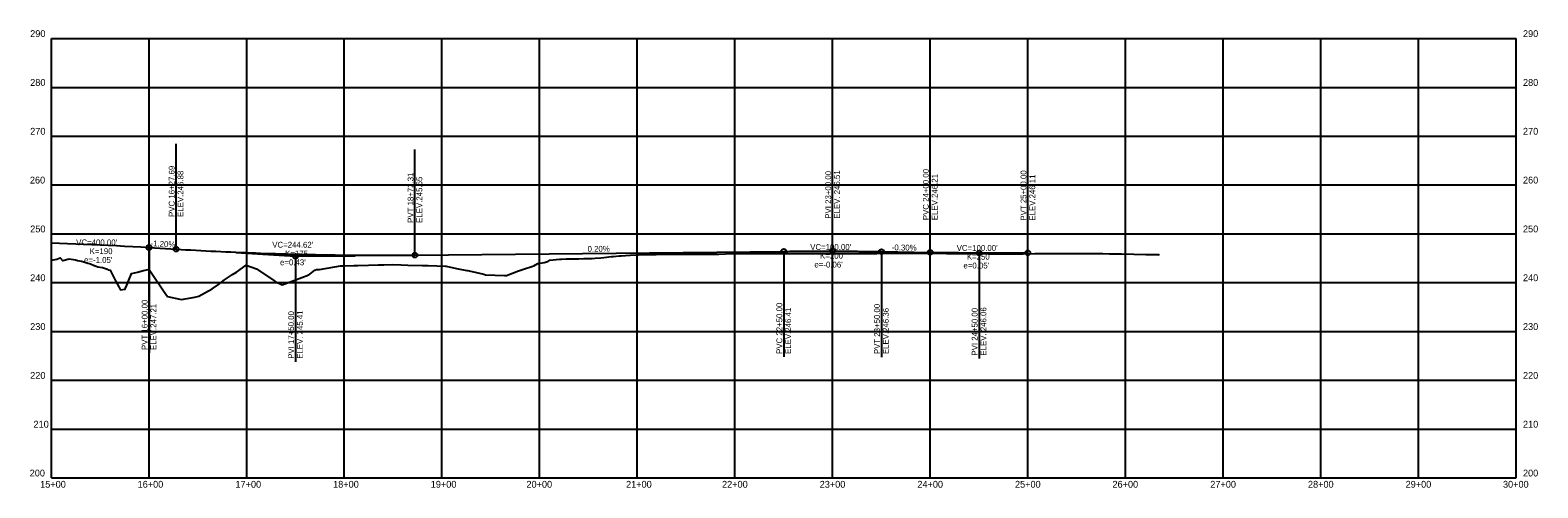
# Model space of a CAD drawing. Extents: x 1939726 to 1943270, y 529766 to 530234.
# Drawn here: x 1941726 to 1943270, y 529766 to 530234 of the extents above; entities that cross this region are included whole.
import ezdxf

# ---------------------------------------------------------------- set-up
doc = ezdxf.new("R2010")
doc.units = 0
for name, color, linetype in [('R_Axis', 7, 'Continuous'), ('R_Axis Annot', 7, 'Continuous'), ('R_Exist Surface', 7, 'Continuous'), ('R_Grid', 7, 'Continuous'), ('R_Vert Alg', 7, 'Continuous'), ('R_Vert Alg Annot', 7, 'Continuous')]:
    doc.layers.add(name, color=color, linetype=linetype)

msp = doc.modelspace()

# ---------------------------------------------------------------- linework, layer by layer
at = {"layer": 'R_Axis'}
for p, q in [((1941747.8, 529775.8), (1941747.8, 530225.8)), ((1943247.8, 529775.8), (1943247.8, 530225.8)), ((1941747.8, 529775.8), (1943247.8, 529775.8))]:
    msp.add_line(p, q, dxfattribs=at)
at = {"layer": 'R_Exist Surface'}
msp.add_lwpolyline([(1941747.8, 529998.9), (1941753.4, 529999.8), (1941753.4, 529999.8), (1941756.7, 530001.3), (1941759.4, 529998.3), (1941759.7, 529998.4), (1941766, 530000.3), (1941766.1, 530000.3), (1941772.4, 529999), (1941774.6, 529998.6), (1941778.8, 529997.7), (1941780.9, 529997.2), (1941785.1, 529995.8), (1941787.8, 529994.9), (1941791.5, 529993.4), (1941793.8, 529992.5), (1941795.5, 529992), (1941797.8, 529991.6), (1941800.2, 529991.2), (1941804.1, 529990), (1941805.1, 529989.7), (1941806.1, 529989), (1941808.1, 529988.6), (1941810.5, 529983.7), (1941813.4, 529977.7), (1941816.8, 529971.5), (1941818.4, 529968.7), (1941818.6, 529968.5), (1941823, 529969.2), (1941823.2, 529969.2), (1941823.2, 529969.3), (1941823.8, 529970.2), (1941825, 529973.3), (1941827.8, 529980), (1941829.5, 529984), (1941830, 529985.1), (1941835.9, 529986.6), (1941842.2, 529988.2), (1941847, 529989.3), (1941848.2, 529988.6), (1941848.5, 529988.2), (1941850.7, 529985), (1941862.5, 529967.3), (1941866.7, 529961.5), (1941879.2, 529959), (1941881, 529958.4), (1941894.7, 529960.8), (1941898.8, 529961.9), (1941912.6, 529969.4), (1941919.1, 529974), (1941925.1, 529978.7), (1941933.4, 529984.1), (1941937.3, 529986.6), (1941947.4, 529993.7), (1941957.7, 529990.1), (1941976.5, 529977.3), (1941976.8, 529977.2), (1941976.9, 529977.1), (1941977, 529977.1), (1941984.2, 529973.7), (1942004.2, 529981.2), (1942011.4, 529983.9), (1942012.4, 529984.6), (1942017.5, 529988.5), (1942019.4, 529989.1), (1942022.5, 529989.2), (1942044, 529993.1), (1942046.1, 529993.1), (1942057.7, 529993.5), (1942061.7, 529993.5), (1942072.6, 529993.8), (1942082.4, 529994.1), (1942088.3, 529994), (1942097.2, 529994.3), (1942105.9, 529994), (1942113, 529993.7), (1942127.8, 529993.4), (1942131.3, 529993.3), (1942133.6, 529993.2), (1942151.5, 529992.8), (1942151.8, 529992.8), (1942152.2, 529992.7), (1942162.6, 529990.3), (1942173.3, 529988.3), (1942174.2, 529988.2), (1942175.6, 529987.9), (1942190.7, 529984.4), (1942192.5, 529983.9), (1942202.1, 529983.4), (1942211.9, 529983.2), (1942213, 529983.2), (1942214, 529983.2), (1942226.3, 529987.8), (1942228.3, 529988.6), (1942228.7, 529988.7), (1942229.4, 529988.9), (1942241.7, 529993), (1942246, 529995.3), (1942252.3, 529996.5), (1942256.1, 529997.3), (1942258.2, 529998.9), (1942268, 529999.7), (1942269.4, 529999.8), (1942269.9, 529999.8), (1942270.3, 529999.9), (1942274.9, 530000.3), (1942287.8, 530000.1), (1942292.9, 530000.4), (1942301.6, 530000.5), (1942304.7, 530000.7), (1942310.5, 530001.2), (1942313.6, 530001.5), (1942321.5, 530002.4), (1942322.5, 530002.5), (1942323.3, 530002.6), (1942329.2, 530003.2), (1942331.4, 530003.3), (1942335.7, 530003.5), (1942340.3, 530003.8), (1942340.6, 530003.8), (1942349.2, 530004.3), (1942352.8, 530004.6), (1942358, 530004.6), (1942358.1, 530004.6), (1942359.2, 530004.6), (1942367, 530004.7), (1942375.9, 530004.8), (1942378.1, 530004.8), (1942383.5, 530004.9), (1942384.8, 530004.9), (1942393.7, 530004.9), (1942397.9, 530004.9), (1942402.6, 530005), (1942407.6, 530005), (1942411.5, 530005), (1942420.4, 530005.1), (1942421.7, 530005.1), (1942429.3, 530005.1), (1942431.4, 530005.1), (1942438.2, 530005.3), (1942447.1, 530005.5), (1942450.6, 530005.5), (1942456, 530005.6), (1942456.1, 530005.6), (1942459.9, 530005.6), (1942464.9, 530005.6), (1942473.8, 530005.6), (1942475.6, 530005.6), (1942482.7, 530005.5), (1942491.6, 530005.5), (1942493.5, 530005.5), (1942494.9, 530005.5), (1942500.5, 530005.5), (1942509.4, 530005.6), (1942518.3, 530005.6), (1942519.4, 530005.6), (1942519.7, 530005.6), (1942520, 530005.6), (1942527.2, 530005.7), (1942527.9, 530005.7), (1942536.1, 530005.7), (1942544.3, 530005.7), (1942544.5, 530005.7), (1942545, 530005.7), (1942553.9, 530005.7), (1942568, 530005.8), (1942568.6, 530005.8), (1942569.3, 530005.8), (1942592.7, 530005.8), (1942593.2, 530005.8), (1942616.7, 530006), (1942616.8, 530006), (1942616.9, 530006), (1942626.4, 530006), (1942640.8, 530006.1), (1942641, 530006.1), (1942664.4, 530005.8), (1942664.9, 530005.8), (1942665.4, 530005.8), (1942688.4, 530005.5), (1942689.1, 530005.5), (1942708.3, 530005.4), (1942709.8, 530005.4), (1942728.7, 530005.3), (1942730.4, 530005.3), (1942742.1, 530005.4), (1942743, 530005.4), (1942754.9, 530005.5), (1942755.6, 530005.5), (1942767.7, 530005.5), (1942768.2, 530005.6), (1942780.5, 530005.6), (1942780.8, 530005.6), (1942793.2, 530005.6), (1942793.6, 530005.6), (1942806, 530005.5), (1942818.6, 530005.5), (1942818.7, 530005.5), (1942824.4, 530005.5), (1942831.3, 530005.4), (1942839.8, 530005.3), (1942843.8, 530005.2), (1942843.8, 530005.2), (1942856.2, 530005), (1942856.3, 530005), (1942868.7, 530004.7), (1942868.9, 530004.7), (1942881.2, 530004.5), (1942881.4, 530004.5), (1942881.9, 530003.5)], dxfattribs=at)
at = {"layer": 'R_Grid'}
for p, q in [((1941747.8, 530225.8), (1943247.8, 530225.8)), ((1941747.8, 530225.8), (1943247.8, 530225.8)), ((1941847.8, 529775.8), (1941847.8, 530225.8)), ((1941947.8, 529775.8), (1941947.8, 530225.8)), ((1942047.8, 529775.8), (1942047.8, 530225.8)), ((1942147.8, 529775.8), (1942147.8, 530225.8)), ((1942247.8, 529775.8), (1942247.8, 530225.8)), ((1942347.8, 529775.8), (1942347.8, 530225.8)), ((1942447.8, 529775.8), (1942447.8, 530225.8)), ((1942547.8, 529775.8), (1942547.8, 530225.8)), ((1942647.8, 529775.8), (1942647.8, 530225.8)), ((1942747.8, 529775.8), (1942747.8, 530225.8)), ((1942847.8, 529775.8), (1942847.8, 530225.8)), ((1942947.8, 529775.8), (1942947.8, 530225.8)), ((1943047.8, 529775.8), (1943047.8, 530225.8)), ((1943147.8, 529775.8), (1943147.8, 530225.8)), ((1941747.8, 530175.8), (1943247.8, 530175.8)), ((1941747.8, 530125.8), (1943247.8, 530125.8)), ((1941747.8, 530075.8), (1943247.8, 530075.8)), ((1941747.8, 530025.8), (1943247.8, 530025.8)), ((1941747.8, 529975.8), (1943247.8, 529975.8)), ((1941747.8, 529925.8), (1943247.8, 529925.8)), ((1941747.8, 529875.8), (1943247.8, 529875.8)), ((1941747.8, 529825.8), (1943247.8, 529825.8))]:
    msp.add_line(p, q, dxfattribs=at)
at = {"layer": 'R_Vert Alg'}
for p, q in [((1941847.8, 530011.8), (1941875.5, 530010.1)), ((1941936.6, 530006.5), (1941997.8, 530002.8)), ((1942120.1, 530004), (1942497.8, 530007.8)), ((1942522.8, 530008.1), (1942547.8, 530008.3)), ((1942547.8, 530008.3), (1942572.8, 530007.9)), ((1942597.8, 530007.6), (1942647.8, 530006.8)), ((1942672.8, 530006.4), (1942697.8, 530006.1)), ((1942697.8, 530006.1), (1942722.8, 530006.2)), ((1941997.8, 530002.8), (1942058.9, 530003.4))]:
    msp.add_line(p, q, dxfattribs=at)
for points in [[(1941747.8, 530016.5), (1941756.1, 530016.2), (1941764.4, 530015.9), (1941772.8, 530015.6), (1941781.1, 530015.2), (1941789.4, 530014.9), (1941797.8, 530014.5), (1941806.1, 530014.1), (1941814.4, 530013.7), (1941822.8, 530013.2), (1941831.1, 530012.8), (1941839.4, 530012.3), (1941847.8, 530011.8)], [(1941875.5, 530010.1), (1941880.6, 530009.8), (1941885.6, 530009.5), (1941890.7, 530009.3), (1941895.8, 530009), (1941900.9, 530008.7), (1941906, 530008.4), (1941911.1, 530008.2), (1941916.2, 530007.9), (1941921.3, 530007.7), (1941926.4, 530007.5), (1941931.5, 530007.2), (1941936.6, 530007), (1941941.7, 530006.8), (1941946.8, 530006.6), (1941951.9, 530006.4), (1941957, 530006.2), (1941962.1, 530006), (1941967.2, 530005.8), (1941972.3, 530005.7), (1941977.4, 530005.5), (1941982.5, 530005.4), (1941987.6, 530005.2), (1941992.7, 530005.1), (1942002.9, 530004.8), (1942008, 530004.7), (1942013.1, 530004.6), (1942018.2, 530004.5), (1942023.2, 530004.4), (1942028.3, 530004.3), (1942033.4, 530004.2), (1942038.5, 530004.2), (1942043.6, 530004.1), (1942048.7, 530004), (1942053.8, 530004), (1942058.9, 530004), (1942064, 530003.9), (1942069.1, 530003.9), (1942074.2, 530003.9), (1942079.3, 530003.9), (1942084.4, 530003.9), (1942089.5, 530003.9), (1942094.6, 530003.9), (1942099.7, 530003.9), (1942104.8, 530003.9), (1942109.9, 530003.9), (1942115, 530004), (1942120.1, 530004)], [(1942497.8, 530007.8), (1942499.8, 530007.8), (1942501.9, 530007.8), (1942504, 530007.9), (1942506.1, 530007.9), (1942508.2, 530007.9), (1942510.3, 530007.9), (1942512.3, 530007.9), (1942514.4, 530007.9), (1942516.5, 530007.9), (1942518.6, 530008), (1942520.7, 530008), (1942522.8, 530008), (1942524.8, 530008), (1942526.9, 530008), (1942529, 530008), (1942531.1, 530008), (1942533.2, 530008), (1942535.3, 530008), (1942537.3, 530008), (1942539.4, 530008), (1942541.5, 530008), (1942543.6, 530008), (1942545.7, 530008), (1942549.8, 530008), (1942551.9, 530008), (1942554, 530008), (1942556.1, 530008), (1942558.2, 530008), (1942560.3, 530007.9), (1942562.3, 530007.9), (1942564.4, 530007.9), (1942566.5, 530007.9), (1942568.6, 530007.9), (1942570.7, 530007.9), (1942572.8, 530007.9), (1942574.8, 530007.8), (1942576.9, 530007.8), (1942579, 530007.8), (1942581.1, 530007.8), (1942583.2, 530007.7), (1942585.3, 530007.7), (1942587.3, 530007.7), (1942589.4, 530007.7), (1942591.5, 530007.6), (1942593.6, 530007.6), (1942595.7, 530007.6), (1942597.8, 530007.6)], [(1942647.8, 530006.8), (1942649.8, 530006.8), (1942651.9, 530006.7), (1942654, 530006.7), (1942656.1, 530006.7), (1942658.2, 530006.7), (1942660.3, 530006.6), (1942662.3, 530006.6), (1942664.4, 530006.6), (1942666.5, 530006.6), (1942668.6, 530006.5), (1942670.7, 530006.5), (1942672.8, 530006.5), (1942674.8, 530006.5), (1942676.9, 530006.5), (1942679, 530006.4), (1942681.1, 530006.4), (1942683.2, 530006.4), (1942685.3, 530006.4), (1942687.3, 530006.4), (1942689.4, 530006.4), (1942691.5, 530006.3), (1942693.6, 530006.3), (1942695.7, 530006.3), (1942699.8, 530006.3), (1942701.9, 530006.3), (1942704, 530006.3), (1942706.1, 530006.3), (1942708.2, 530006.3), (1942710.3, 530006.3), (1942712.3, 530006.3), (1942714.4, 530006.3), (1942716.5, 530006.2), (1942718.6, 530006.2), (1942720.7, 530006.2), (1942722.8, 530006.2), (1942724.8, 530006.2), (1942726.9, 530006.2), (1942729, 530006.2), (1942731.1, 530006.3), (1942733.2, 530006.3), (1942735.3, 530006.3), (1942737.3, 530006.3), (1942739.4, 530006.3), (1942741.5, 530006.3), (1942743.6, 530006.3), (1942745.7, 530006.3), (1942747.8, 530006.3)]]:
    msp.add_lwpolyline(points, dxfattribs=at)
at = {"layer": 'R_Vert Alg Annot'}
for p, q in [((1941875.5, 530040.1), (1941875.5, 530118.1)), ((1942547.8, 530038.3), (1942547.8, 530116.3)), ((1942647.8, 530036.8), (1942647.8, 530114.8)), ((1942747.8, 530036.3), (1942747.8, 530114.3)), ((1942120.1, 530034), (1942120.1, 530112)), ((1941875.5, 530010.1), (1941875.5, 530040.1)), ((1942547.8, 530008.3), (1942547.8, 530038.3)), ((1942120.1, 530004), (1942120.1, 530034)), ((1942647.8, 530006.8), (1942647.8, 530036.8)), ((1942747.8, 530006.3), (1942747.8, 530036.3)), ((1941847.8, 530011.8), (1941847.8, 529981.8)), ((1942497.8, 530007.8), (1942497.8, 529977.8)), ((1942597.8, 530007.6), (1942597.8, 529977.6)), ((1942697.8, 530006.1), (1942697.8, 529976.1)), ((1941997.8, 530002.8), (1941997.8, 529972.8)), ((1941847.8, 529981.8), (1941847.8, 529903.8)), ((1942497.8, 529977.8), (1942497.8, 529899.8)), ((1942597.8, 529977.6), (1942597.8, 529899.6)), ((1942697.8, 529976.1), (1942697.8, 529898.1)), ((1941997.8, 529972.8), (1941997.8, 529894.8))]:
    msp.add_line(p, q, dxfattribs=at)
for centre in [(1941847.8, 530011.8), (1941875.5, 530010.1), (1942120.1, 530004), (1942497.8, 530007.8), (1942547.8, 530008.3), (1942597.8, 530007.6), (1942647.8, 530006.8), (1942697.8, 530006.1), (1942747.8, 530006.3), (1941997.8, 530002.8)]:
    msp.add_circle(centre, 2.5, dxfattribs=at)

# ---------------------------------------------------------------- texts
at = {"layer": 'R_Axis Annot'}
for s, height, p in [('290', 7, (1941726.1, 530227.3)), ('290', 7, (1941726.1, 530227.3)), ('290', 7, (1943254.8, 530227.3)), ('290', 7, (1943254.8, 530227.3)), ('280', 7, (1941726.1, 530177.3)), ('280', 7, (1943254.8, 530177.3)), ('270', 7, (1941726.1, 530127.3)), ('270', 7, (1943254.8, 530127.3)), ('260', 7, (1941725.8, 530077.3)), ('260', 7, (1943254.8, 530077.3)), ('250', 7, (1941726.1, 530027.3)), ('250', 7, (1943254.8, 530027.3)), ('240', 7, (1941726.1, 529977.3)), ('240', 7, (1943254.8, 529977.3)), ('230', 7, (1941726.1, 529927.3)), ('230', 7, (1943254.8, 529927.3)), ('220', 7, (1941726.1, 529877.3)), ('220', 7, (1943254.8, 529877.3)), ('210', 7, (1941729.5, 529827.3)), ('210', 7, (1943254.8, 529827.3)), ('200', 7, (1941725.6, 529777.3)), ('-', 0.0001, (1941747.8, 529775.8)), ('200', 7, (1943254.8, 529777.3)), ('15+00', 7, (1941736.3, 529765.8)), ('16+00', 7, (1941836.1, 529765.8)), ('17+00', 7, (1941936.3, 529765.8)), ('18+00', 7, (1942036.3, 529765.8)), ('19+00', 7, (1942136.3, 529765.8)), ('20+00', 7, (1942234.3, 529765.8)), ('21+00', 7, (1942336.3, 529765.8)), ('22+00', 7, (1942434.6, 529765.8)), ('23+00', 7, (1942534.6, 529765.8)), ('24+00', 7, (1942634.6, 529765.8)), ('25+00', 7, (1942734.6, 529765.8)), ('26+00', 7, (1942834.4, 529765.8)), ('27+00', 7, (1942934.6, 529765.8)), ('28+00', 7, (1943034.6, 529765.8)), ('29+00', 7, (1943134.6, 529765.8)), ('30+00', 7, (1943234.3, 529765.8))]:
    msp.add_text(s, height=height, dxfattribs=at).set_placement(p)
at = {"layer": 'R_Vert Alg Annot'}
for s, rotation, p in [('PVC 16+27.69', 90, (1941874, 530043.1)), ('ELEV.246.88', 90, (1941883, 530043.1)), ('PVT 18+72.31', 90, (1942118.6, 530037)), ('ELEV.245.65', 90, (1942127.6, 530037)), ('PVI 23+00.00', 90, (1942546.3, 530041.3)), ('ELEV. 246.51', 90, (1942555.3, 530041.3)), ('PVC 24+00.00', 90, (1942646.3, 530039.8)), ('ELEV.246.21', 90, (1942655.3, 530039.8)), ('PVT 25+00.00', 90, (1942746.3, 530039.3)), ('ELEV.246.11', 90, (1942755.3, 530039.3)), ('-1.20%', 356.5664, (1941849.2, 530013.2)), ('0.20%', 0.5729, (1942296.9, 530007.3)), ('-0.30%', 359.1406, (1942608.4, 530008.9)), ('PVT 16+00.00', 90, (1941846.3, 529906.8)), ('ELEV.247.21', 90, (1941855.3, 529906.8)), ('PVI 17+50.00', 90, (1941996.3, 529897.8)), ('ELEV. 245.41', 90, (1942005.3, 529897.8)), ('PVC 22+50.00', 90, (1942496.3, 529902.8)), ('ELEV.246.41', 90, (1942505.3, 529902.8)), ('PVT 23+50.00', 90, (1942596.3, 529902.6)), ('ELEV.246.36', 90, (1942605.3, 529902.6)), ('PVI 24+50.00', 90, (1942696.3, 529901.1)), ('ELEV. 246.06', 90, (1942705.3, 529901.1))]:
    msp.add_text(s, height=6, rotation=rotation, dxfattribs=at).set_placement(p)
for s, p in [("VC=400.00'", (1941773.2, 530014)), ('K=190', (1941787, 530005)), ("VC=244.62'", (1941974, 530011.6)), ('K=175', (1941987.2, 530002.6)), ("VC=100.00'", (1942524.9, 530009.3)), ('K=200', (1942535, 530000.3)), ("VC=100.00'", (1942674.9, 530008.3)), ("e=-1.05'", (1941781.3, 529996)), ("e=0.43'", (1941982, 529993.6)), ("e=-0.06'", (1942529.2, 529991.3)), ("e=0.05'", (1942681.8, 529990.3)), ('K=250', (1942685.3, 529999.3))]:
    msp.add_text(s, height=6, dxfattribs=at).set_placement(p)

doc.saveas('drawing.dxf')
